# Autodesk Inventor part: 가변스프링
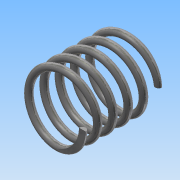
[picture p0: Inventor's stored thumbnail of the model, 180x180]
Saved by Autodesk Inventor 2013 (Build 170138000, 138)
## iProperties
Created: 2017-12
Part Number: 가변스프링
Material: 스테인리스강
Document SubType Name: Modeling
Designer: Administrator
Density: 8.08 g/cm^3
Mass: 7.06913 g
Surface Area: 17.7394 cm^2
Volume: 0.874892 cm^3
Author: Administrator
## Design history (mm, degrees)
sketch "스케치1"
  geometry: L1 (0, 0)-(9, 0); L2 (0, 0)-(0, 28.5); L3 (0, 28.5)-(19.49, 28.5); C1 r 1 at (9, 0)
  constraints: 6 end point, 2 perpendicular, 1 centre point, 1 coincident, 1 horizontal
  dimensions: "d0" = 28.5 distance of L1.start L2.end (derived); "d1" = 9 distance of L1.start L1.end; "d2" = 2 diameter of C1
feature "코일1" sketch "스케치1" pitch "d3" = 10; turns "d5" = 5; dims "d4" = 28.5 (= d0), "d6" = 0, angle "d7" = 90 deg, angle "d8" = 90 deg, "d9" = 0, "d10" = 0
sketch "스케치2"
  geometry: L1 (0, 12.5)-(28.5, 12.5); L2 (28.5, 12.5)-(28.5, -12.5); L3 (28.5, -12.5)-(0, -12.5); L4 (0, -12.5)-(0, 12.5); 2 further points
  constraints: 8 end point, 2 parallel, 1 coincident, 1 horizontal, 1 midpoint, 1 perpendicular
  dimensions: "d11" = 25 distance of L1.end L2.end; "d13" = 28.5 distance of L1.start L1.end (derived)
extrude "돌출1" sketch "스케치2" stored distance "d14" = 30; taper "d15" = 0 deg
node "솔리드1"
